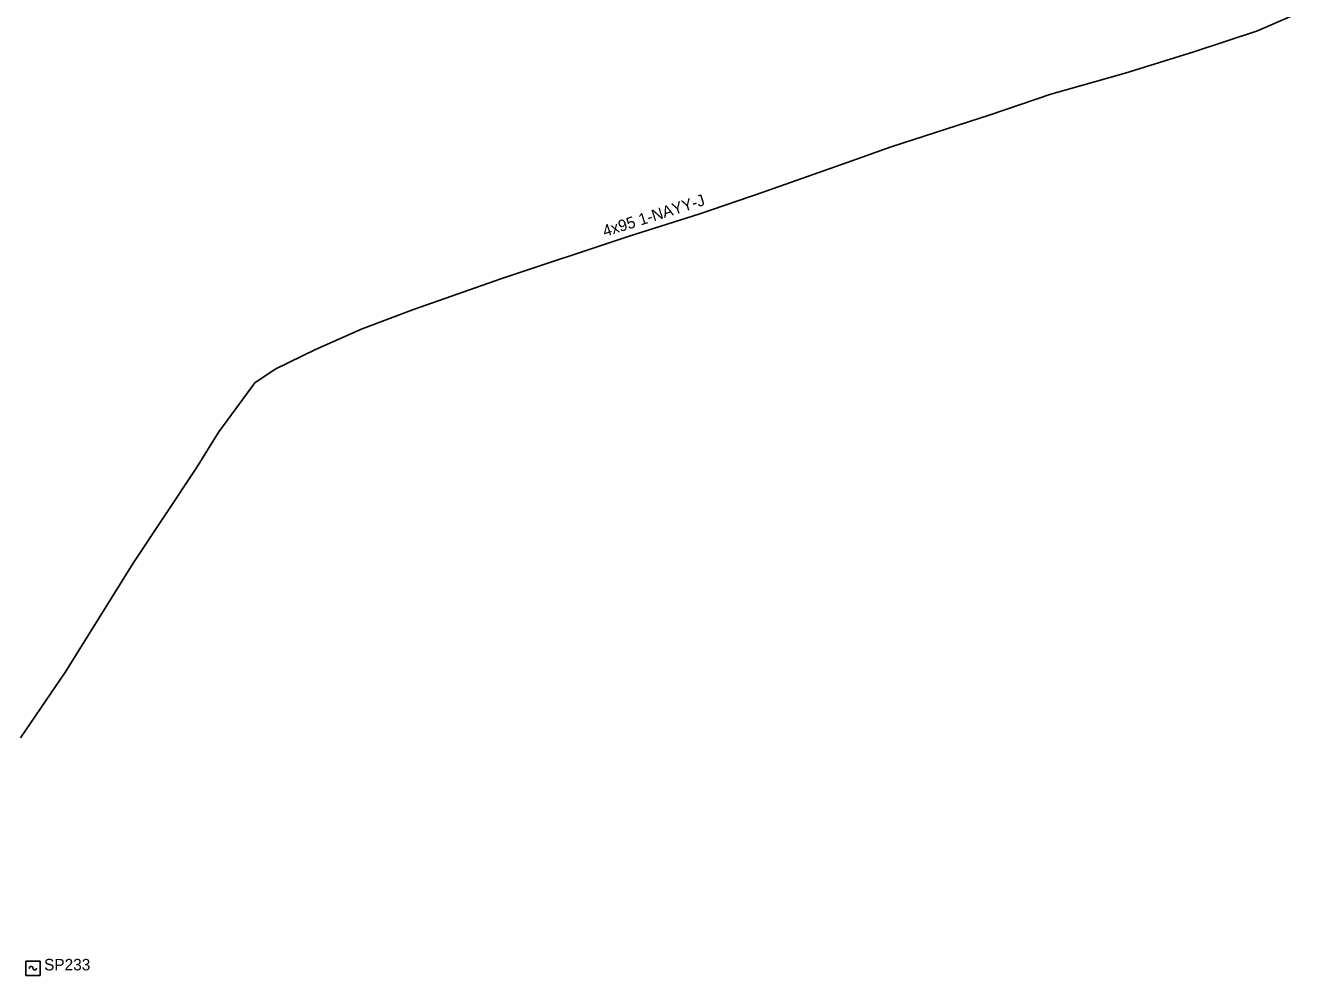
# Model space of a CAD drawing. Extents: x -763093 to -760976, y -1155572 to -1152009.
# Drawn here: x -761579.1 to -761467.7, y -1155124 to -1155041.4 of the extents above; entities that cross this region are included whole.
import ezdxf

# ---------------------------------------------------------------- set-up
doc = ezdxf.new("R2010")
doc.units = 0
for name, color, linetype in [('Vrstva 1', 7, 'Continuous'), ('Vrstva 33', 7, 'Continuous'), ('Vrstva 34', 7, 'Continuous'), ('Vrstva 5', 7, 'Continuous'), ('Vrstva 6', 7, 'Continuous')]:
    doc.layers.add(name, color=color, linetype=linetype)

# ---------------------------------------------------------------- blocks, each defined once
blk = doc.blocks.new('NN740')
at = {"layer": 'Vrstva 1'}
for points in [[(0.62, 0.62), (-0.63, 0.62)], [(-0.63, 0.62), (-0.63, -0.63)], [(0, 0), (0, 0.01), (0, 0.03), (-0.01, 0.05), (-0.01, 0.06), (-0.02, 0.08), (-0.03, 0.09), (-0.04, 0.1), (-0.05, 0.11), (-0.06, 0.12), (-0.08, 0.13), (-0.09, 0.14), (-0.11, 0.14), (-0.12, 0.15), (-0.14, 0.15), (-0.15, 0.15), (-0.17, 0.15), (-0.18, 0.15), (-0.2, 0.15), (-0.21, 0.14), (-0.23, 0.13), (-0.24, 0.12), (-0.26, 0.11), (-0.27, 0.1), (-0.28, 0.09), (-0.29, 0.08), (-0.29, 0.06), (-0.3, 0.05), (-0.3, 0.03), (-0.31, 0.02), (-0.31, 0), (-0.31, 0)], [(0.62, -0.63), (0.62, 0.62)], [(-0.63, -0.63), (0.62, -0.63)], [(0, 0), (0, -0.02), (0, -0.03), (0.01, -0.05), (0.01, -0.06), (0.02, -0.08), (0.03, -0.09), (0.04, -0.1), (0.05, -0.11), (0.06, -0.12), (0.07, -0.13), (0.09, -0.14), (0.1, -0.15), (0.12, -0.15), (0.13, -0.15), (0.15, -0.15), (0.16, -0.15), (0.18, -0.15), (0.19, -0.15), (0.21, -0.14), (0.22, -0.14), (0.24, -0.13), (0.25, -0.12), (0.26, -0.11), (0.27, -0.09), (0.28, -0.08), (0.29, -0.07), (0.29, -0.05), (0.3, -0.04), (0.3, -0.02), (0.3, -0.01), (0.3, -0.01)]]:
    blk.add_lwpolyline(points, dxfattribs=at)

msp = doc.modelspace()

# ---------------------------------------------------------------- linework, layer by layer
at = {"layer": 'Vrstva 5'}
msp.add_lwpolyline([(-761579.55, -1155103.39), (-761575.64, -1155097.65), (-761569.77, -1155088.19), (-761564.24, -1155079.89), (-761562.3, -1155076.76), (-761559.18, -1155072.52), (-761557.42, -1155071.33), (-761553.9, -1155069.61), (-761549.84, -1155067.8), (-761545.38, -1155066.13), (-761537.77, -1155063.46), (-761526.71, -1155059.79), (-761520.47, -1155057.81), (-761515.06, -1155055.97), (-761507.67, -1155053.35), (-761503.84, -1155051.99), (-761495.22, -1155049.19), (-761489.97, -1155047.4), (-761483.5, -1155045.58), (-761477.52, -1155043.71), (-761471.99, -1155041.91), (-761467.74, -1155040.05)], dxfattribs=at)

# ---------------------------------------------------------------- block references
at = {"layer": 'Vrstva 34'}
msp.add_blockref('NN740', (-761578.47, -1155123.41), dxfattribs=at)

# ---------------------------------------------------------------- texts
at = {"layer": 'Vrstva 33'}
msp.add_text('SP233', height=1, dxfattribs=at).set_placement((-761577.5, -1155123.6))
at = {"layer": 'Vrstva 6'}
msp.add_text('4x95 1-NAYY-J', height=1, rotation=17.605, dxfattribs=at).set_placement((-761528.74, -1155059.82))

doc.saveas('drawing.dxf')
